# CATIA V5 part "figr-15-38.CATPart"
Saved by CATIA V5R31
Part number: Part1
Bounding box of the stored display mesh (mm): x -63.331 to 69.186, y -39.139 to 39.139, z 0 to 69.963
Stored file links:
  D:\PROJECTS\Project 2021\US EDITION\CATIA V5 6R 2021\Resources\Part Files\c15_catia_v5_6r2021_prt\figr-15-38.CATPart
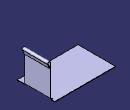
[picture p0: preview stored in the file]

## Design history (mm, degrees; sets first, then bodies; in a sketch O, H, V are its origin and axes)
SheetMetalParameters1: Thickness 1, BendRadius 2, KFactor 0.400515 {= log(min(100,max(20*SheetMetalParameters1.BendRadius,SheetMetalParameters1.Thickness)/SheetMetalParameters1.Thickness))/log(100)/2}, ReliefRadialLength 1, ReliefAxialLength 2, MinimumBendRadius 0
Body1 (main body)
  Sketch1 on xy-plane, origin (0, 0, 0), H (1, 0, 0), V (0, 1, 0)
    line L1 (-63.3311, 39.1393) -> (63.3311, 39.1393)
    line L2 (63.3311, 39.1393) -> (63.3311, -39.1393)
    line L3 (63.3311, -39.1393) -> (-63.3311, -39.1393)
    line L4 (-63.3311, -39.1393) -> (-63.3311, 39.1393)
    horizontal: L1 H, L3 H
    vertical: L2 V, L4 V
    symmetry: L4 L2 V, L1 L3 H
  Wall1: Thickness 1, Profile Sketch1
  d_NewWallOnEdge1: NewWallOnEdge_Edge edge [face of Wall1 | face of Wall1], NewWallOnEdge_Length 67, NewWallOnEdge_HeightLimitOffset 0, NewWallOnEdge_WidthOffset1 -16, NewWallOnEdge_WidthOffset2 -9, NewWallOnEdge_Angle 90, NewWallOnEdge_BendRadiusValue 2 {= SheetMetalParameters1.BendRadius}, NewWallOnEdge_BendTable SheetMetalParameters1, KFacteur 0.400515 {= log(min(100,max(20*d_NewWallOnEdge1.Radius,SheetMetalParameters1.Thickness)/SheetMetalParameters1.Thickness))/log(100)/2}
  Flange1: Angle 22.6199 {= 2*atan(Flange1.Radius/Flange1.Length)}, Length 10, Radius 2, KFacteur 0.400515 {= log(min(100,max(20*Flange1.Radius,SheetMetalParameters1.Thickness)/SheetMetalParameters1.Thickness))/log(100)/2}, Guide edge [face of d_NewWallOnEdge1 | face of d_NewWallOnEdge1]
